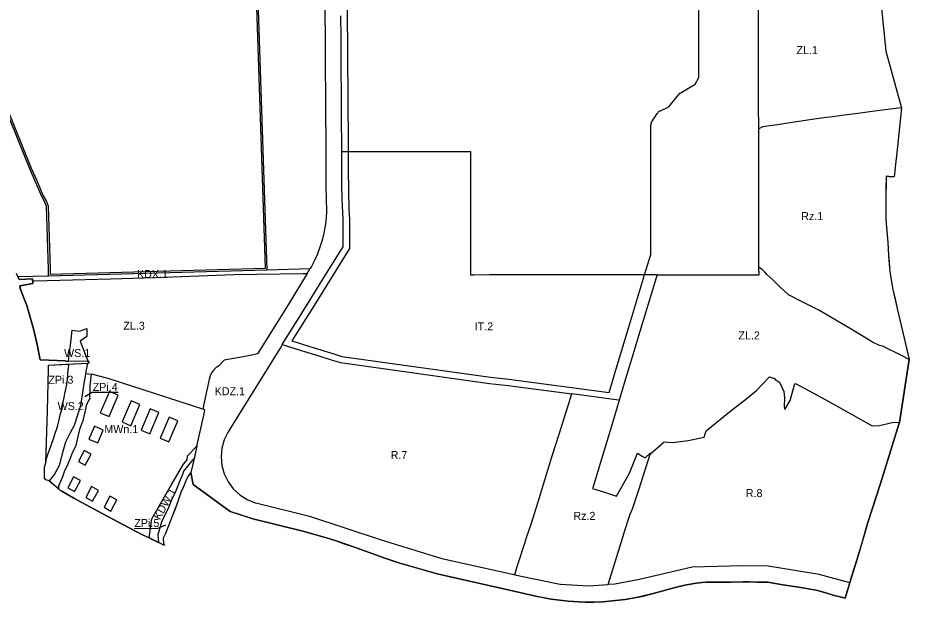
# Model space of a CAD drawing. Extents: x 7434685 to 7436459, y 5545868 to 5548111.
# Drawn here: x 7435281 to 7436395, y 5545868 to 5546598 of the extents above; entities that cross this region are included whole.
import ezdxf

# ---------------------------------------------------------------- set-up
doc = ezdxf.new("R2010")
doc.units = 0
for name, color, linetype in [('LIN_Granica Planu', 7, 'Continuous'), ('LIN_linia regulacyjna_1', 7, 'Continuous'), ('LIN_Linia Zabudowy Nieprzekraczalna', 7, 'Continuous'), ('LIN_Linia Zabudowy Obowiązujaca', 7, 'Continuous'), ('LIN_Linie Rozgraniczajace', 7, 'Continuous'), ('TXT_Oznaczenia Przeznaczenia', 7, 'Continuous')]:
    doc.layers.add(name, color=color, linetype=linetype)

msp = doc.modelspace()

# ---------------------------------------------------------------- linework, layer by layer
at = {"layer": 'LIN_Granica Planu'}
msp.add_lwpolyline([(7436359.2, 5546623), (7436366, 5546556.9), (7436385.4, 5546486.1), (7436382, 5546453.8), (7436380.6, 5546437.9), (7436378, 5546415.1), (7436376.2, 5546399.7), (7436370.9, 5546400), (7436368.3, 5546400.3), (7436366.1, 5546400.5), (7436365.8, 5546367.1), (7436365.7, 5546347.3), (7436365.8, 5546346.4), (7436368.5, 5546317.8), (7436369.3, 5546301.6), (7436370.6, 5546285.6), (7436371.2, 5546279.2), (7436373.8, 5546263.5), (7436374.6, 5546259), (7436380.1, 5546235.4), (7436395, 5546171.7), (7436383, 5546092.9), (7436381, 5546086.6), (7436359.3, 5546016.7), (7436348.6, 5545984.5), (7436343.5, 5545967.9), (7436340.8, 5545959.2), (7436329.7, 5545921), (7436322.1, 5545897.1), (7436314.8, 5545873.5), (7436307, 5545875.5), (7436303.1, 5545876.5), (7436298.9, 5545877.6), (7436292, 5545879.8), (7436285.1, 5545881.6), (7436278.7, 5545883.3), (7436254.1, 5545887.4), (7436236.9, 5545890.2), (7436218.2, 5545893.3), (7436210, 5545893.4), (7436204.4, 5545893.6), (7436195.5, 5545893.7), (7436187.6, 5545893.7), (7436171.9, 5545893.5), (7436141.3, 5545893.2), (7436136.1, 5545892.8), (7436128.9, 5545892.2), (7436114.8, 5545889.8), (7436102.7, 5545886.7), (7436076.9, 5545879.5), (7436056.3, 5545874.6), (7436040.1, 5545871.7), (7436012, 5545868.8), (7435990.1, 5545868.4), (7435969, 5545869.6), (7435947.7, 5545872.2), (7435941, 5545873.5), (7435929.9, 5545875.7), (7435895.6, 5545883.4), (7435805, 5545903.8), (7435758.6, 5545917.2), (7435741, 5545922.8), (7435700.5, 5545937.4), (7435681.5, 5545944), (7435670.8, 5545947.4), (7435637.1, 5545957.2), (7435574.8, 5545972.5), (7435546.3, 5545981.8), (7435500.1, 5546015.5), (7435497.3, 5546030.5), (7435494.1, 5546025.8), (7435492, 5546021.9), (7435488.4, 5546013.9), (7435485, 5546005.4), (7435480.7, 5545993.1), (7435474.5, 5545976.5), (7435465.7, 5545954.4), (7435462.6, 5545948.3), (7435463, 5545941.4), (7435464.3, 5545939.3), (7435445.4, 5545948.6), (7435437.9, 5545952.3), (7435420.4, 5545961.1), (7435386.4, 5545979.1), (7435351.1, 5545998.5), (7435336, 5546007.2), (7435333.1, 5546008.8), (7435320.4, 5546019.9), (7435316.3, 5546021.2), (7435314.3, 5546023.2), (7435314.4, 5546036.9), (7435315.9, 5546042.6), (7435318.2, 5546107.6), (7435319.4, 5546160.4), (7435319.5, 5546164.4), (7435341.2, 5546165.6), (7435370, 5546167.2), (7435369.9, 5546169.3), (7435340.8, 5546169.4), (7435340.7, 5546170.1), (7435309.2, 5546171), (7435305.4, 5546190.4), (7435300.5, 5546210.1), (7435292.2, 5546239), (7435284.3, 5546259), (7435283.7, 5546263.5), (7435300, 5546266.6), (7435299.5, 5546272.5), (7435282.7, 5546271.5), (7435279.4, 5546278.9)], dxfattribs=at)
at = {"layer": 'LIN_linia regulacyjna_1'}
msp.add_lwpolyline([(7435243.6, 5546543.7), (7435297.9, 5546410.5), (7435304.7, 5546395.2), (7435312.3, 5546376.8), (7435316.9, 5546368.8), (7435318.9, 5546363), (7435321.5, 5546284.9), (7435321.5, 5546278.2), (7435590.7, 5546285.6), (7435571.7, 5546849.8), (7435571.7, 5546850.9), (7435567.9, 5546853), (7435538.3, 5546859.6), (7435397.1, 5546854.4), (7435356.3, 5546852.2), (7435331.6, 5546851.4), (7435319.9, 5546850.7), (7435306.9, 5546850.4), (7435208.7, 5546851.2)], dxfattribs=at)
at = {"layer": 'LIN_Linia Zabudowy Nieprzekraczalna'}
for p, q in [((7436073.4, 5546468.7), (7436080.1, 5546479)), ((7436072, 5546302.7), (7436072, 5546464.3)), ((7436064.4, 5546277.4), (7436072, 5546302.7)), ((7435894.7, 5546146.9), (7436019.9, 5546130.4)), ((7435395.5, 5546131.6), (7435384.2, 5546105.1)), ((7435406.6, 5546126.9), (7435395.5, 5546131.6)), ((7435395.3, 5546100.4), (7435406.6, 5546126.9)), ((7435422.6, 5546120.1), (7435411.3, 5546093.6)), ((7435433.6, 5546115.3), (7435422.6, 5546120.1)), ((7435422.3, 5546088.9), (7435433.6, 5546115.3)), ((7435446.4, 5546109.9), (7435435.1, 5546083.4)), ((7435457.4, 5546105.2), (7435446.4, 5546109.9)), ((7435384.2, 5546105.1), (7435395.3, 5546100.4)), ((7435446.1, 5546078.7), (7435457.4, 5546105.2)), ((7435470.2, 5546099.7), (7435458.9, 5546073.3)), ((7435481.2, 5546095), (7435470.2, 5546099.7)), ((7435376.8, 5546088.2), (7435369.9, 5546072.2)), ((7435387.9, 5546083.5), (7435376.8, 5546088.2)), ((7435411.3, 5546093.6), (7435422.3, 5546088.9)), ((7435469.9, 5546068.6), (7435481.2, 5546095)), ((7435381, 5546067.4), (7435387.9, 5546083.5)), ((7435435.1, 5546083.4), (7435446.1, 5546078.7)), ((7435458.9, 5546073.3), (7435469.9, 5546068.6)), ((7435369.9, 5546072.2), (7435381, 5546067.4))]:
    msp.add_line(p, q, dxfattribs=at)
for points in [[(7435766.5, 5546953.9), (7435690.6, 5546953.9), (7435692.1, 5546706.5), (7435692.3, 5546682.4), (7435692.6, 5546636), (7435692.7, 5546624), (7435692.8, 5546608.2), (7435693.9, 5546441.6), (7435693.9, 5546431.1), (7435693.9, 5546431.1), (7435694, 5546410.7), (7435694.2, 5546381.2), (7435694.9, 5546359.7), (7435695.6, 5546346.7), (7435695.4, 5546331.7), (7435695.7, 5546310.3), (7435684.1, 5546291.7), (7435651.3, 5546239), (7435648.5, 5546234.6), (7435646.4, 5546231.2), (7435623.7, 5546194.8)], [(7436132, 5546524.1), (7436132, 5546850.9), (7435957.9, 5546850.9), (7435957.9, 5546872.1), (7435914, 5546872.1)], [(7436108.8, 5546504.2), (7436127.7, 5546515.4), (7436132, 5546524.1)], [(7436083.2, 5546481.7), (7436094.7, 5546487.4), (7436106.7, 5546502.3)], [(7436019.9, 5546130.4), (7436030.1, 5546164.1), (7436044.2, 5546210.8), (7436064.4, 5546277.4)], [(7435623.7, 5546194.8), (7435644.6, 5546188.4), (7435652.5, 5546185.9)], [(7435652.6, 5546185.9), (7435653.1, 5546185.8), (7435670, 5546180.5)], [(7435670.1, 5546180.5), (7435674.9, 5546178.9), (7435686.2, 5546175.5), (7435871.6, 5546149.7), (7435894.7, 5546146.9)]]:
    msp.add_lwpolyline(points, dxfattribs=at)
for centre, start, end in [((7436112.9, 5546497.3), 120.7481, 141.1626), ((7436086.8, 5546474.6), 116.4028, 146.5734), ((7436080, 5546464.3), 146.5734, 180), ((7435650.2, 5546178.3), 72.4201, 72.8733), ((7435667.6, 5546172.9), 71.9926, 72.8461), ((7435893.7, 5546138.9), 82.5116, 82.9419)]:
    msp.add_arc(centre, 8, start, end, dxfattribs=at)
at = {"layer": 'LIN_Linia Zabudowy Obowiązujaca'}
for p, q in [((7435364.2, 5546057.9), (7435356.8, 5546044.2)), ((7435372.8, 5546053.2), (7435364.2, 5546057.9)), ((7435365.4, 5546039.5), (7435372.8, 5546053.2)), ((7435356.8, 5546044.2), (7435365.4, 5546039.5)), ((7435350.8, 5546024.9), (7435343.5, 5546011.3)), ((7435359.4, 5546020.3), (7435350.8, 5546024.9)), ((7435352.1, 5546006.7), (7435359.4, 5546020.3)), ((7435343.5, 5546011.3), (7435352.1, 5546006.7)), ((7435373.3, 5546012.8), (7435366, 5545999.2)), ((7435381.9, 5546008.1), (7435373.3, 5546012.8)), ((7435374.6, 5545994.5), (7435381.9, 5546008.1)), ((7435366, 5545999.2), (7435374.6, 5545994.5)), ((7435396.2, 5546000.7), (7435388.8, 5545986.9)), ((7435404.7, 5545996.1), (7435396.2, 5546000.7)), ((7435397.3, 5545982.3), (7435404.7, 5545996.1)), ((7435388.8, 5545986.9), (7435397.3, 5545982.3))]:
    msp.add_line(p, q, dxfattribs=at)
at = {"layer": 'LIN_Linie Rozgraniczajace'}
msp.add_line((7435368.8, 5546169.3), (7435344.6, 5546169.4), dxfattribs=at)
for points in [[(7435592.7, 5546283.7), (7435573.9, 5546846), (7435555.2, 5547402.9)], [(7436356.5, 5546690.7), (7436356.8, 5546682.9), (7436357.1, 5546675), (7436359.2, 5546623), (7436366, 5546556.9), (7436385.4, 5546486.1)], [(7435664.8, 5546608.6), (7435665, 5546569.7), (7435665.2, 5546551.1), (7435665.3, 5546530.9), (7435665.4, 5546506.8), (7435665.7, 5546469.7), (7435665.8, 5546454.4), (7435665.8, 5546447.8), (7435665.9, 5546431.5), (7435665.9, 5546428.7), (7435666, 5546422.6), (7435666, 5546422.6), (7435665.9, 5546420.8), (7435665.8, 5546419), (7435665.8, 5546418.5), (7435665.8, 5546415.8), (7435665.8, 5546414), (7435665.8, 5546412.2), (7435665.8, 5546411.3), (7435665.8, 5546410.5), (7435665.9, 5546408.7), (7435665.9, 5546406.9), (7435666, 5546405.2), (7435666, 5546403.4), (7435666.1, 5546400.5), (7435666.1, 5546398.9), (7435666.1, 5546397.9), (7435666.1, 5546396.2), (7435666.1, 5546394.4), (7435666.2, 5546392.6), (7435666.2, 5546390.8), (7435666.2, 5546389.1), (7435666.2, 5546387.3), (7435666.2, 5546386.9), (7435666.3, 5546372.6), (7435666.5, 5546367.9), (7435666.7, 5546362), (7435666.7, 5546356), (7435666.3, 5546348.9), (7435665.9, 5546344.5), (7435665.2, 5546338.7), (7435664.4, 5546334.3), (7435662.9, 5546326.9), (7435661, 5546319.5), (7435659.5, 5546314.6), (7435655.1, 5546302.5), (7435651.8, 5546295.1), (7435651, 5546293.5), (7435649.8, 5546291.2), (7435647.9, 5546287.6), (7435646.4, 5546285.1)], [(7436206.9, 5546459.9), (7436206.9, 5546468.1), (7436206.9, 5546471.8), (7436206.9, 5546471.8), (7436206.8, 5546477.2), (7436206.8, 5546481.7), (7436206.8, 5546486.2), (7436206.5, 5546613.2)], [(7435685.9, 5546431.1), (7435685.8, 5546441), (7435685.8, 5546441.6), (7435685.8, 5546447.4), (7435685.8, 5546453.9), (7435685.7, 5546456.6), (7435685.7, 5546457.7), (7435685.7, 5546469.2), (7435685.4, 5546506.3), (7435685.4, 5546515.3), (7435685.3, 5546521.7), (7435685.3, 5546522.2), (7435685.3, 5546530.5), (7435685.3, 5546534.1), (7435685.2, 5546550.6), (7435685, 5546569.3), (7435685, 5546574.3), (7435684.8, 5546600.8)], [(7435319.5, 5546276.2), (7435319.5, 5546284.9), (7435316.9, 5546362.6), (7435315, 5546368), (7435310.5, 5546375.9), (7435302.8, 5546394.4), (7435296.1, 5546409.7), (7435281.8, 5546444.7), (7435241.8, 5546543)], [(7436385.4, 5546486.1), (7436385.4, 5546486.1), (7436385.4, 5546486.1), (7436375.1, 5546484.8), (7436364.9, 5546483.6), (7436354.8, 5546482.3), (7436342.7, 5546480.7), (7436330.7, 5546479), (7436320.7, 5546477.8), (7436310.7, 5546476.5), (7436299.4, 5546474.9), (7436288.2, 5546473.4), (7436279.5, 5546472.2), (7436270.8, 5546471.1), (7436257.1, 5546468.9), (7436243.3, 5546466.7), (7436230.6, 5546464.9), (7436230.6, 5546464.9), (7436224.2, 5546464), (7436217.8, 5546463.2), (7436214.8, 5546462.7), (7436211.8, 5546462.3), (7436206.9, 5546459.9)], [(7436385.4, 5546486.1), (7436383.7, 5546469.9), (7436382, 5546453.8), (7436381.3, 5546445.8), (7436380.6, 5546437.9), (7436379.2, 5546425.9), (7436378, 5546415.1), (7436377.1, 5546407.4), (7436376.2, 5546399.7), (7436370.9, 5546400), (7436369.6, 5546400.2), (7436368.3, 5546400.3), (7436367.2, 5546400.4), (7436366.1, 5546400.5), (7436365.9, 5546383.8), (7436365.8, 5546367.1), (7436365.8, 5546357.2), (7436365.7, 5546347.3), (7436365.8, 5546346.4), (7436365.8, 5546346.4), (7436367.2, 5546332.1), (7436368.5, 5546317.8), (7436369.3, 5546301.6), (7436370, 5546293.6), (7436370.6, 5546285.6), (7436370.9, 5546282.4), (7436371.2, 5546279.2), (7436373.8, 5546263.5), (7436374.6, 5546259), (7436377.3, 5546247.2), (7436380.1, 5546235.4), (7436387.5, 5546203.6), (7436395, 5546171.7)], [(7436207.3, 5546286.9), (7436207.3, 5546298.2), (7436207.3, 5546309.5), (7436207.2, 5546331.8), (7436207.2, 5546354.1), (7436207.1, 5546374), (7436207.1, 5546393.8), (7436207, 5546402.2), (7436207, 5546410.6), (7436206.9, 5546435.2), (7436206.9, 5546459.9)], [(7435611.6, 5546190.5), (7435634.6, 5546227.3), (7435640.7, 5546237.1), (7435641.5, 5546238.4), (7435641.7, 5546238.8), (7435649.6, 5546251.5), (7435659, 5546266.5), (7435679.7, 5546299.7), (7435681.7, 5546303.2), (7435687.6, 5546312.5), (7435687.6, 5546346.5), (7435686.3, 5546372.2), (7435686.2, 5546389.8), (7435686.2, 5546389.9), (7435686.1, 5546399.6), (7435686, 5546421.6), (7435685.9, 5546428.2), (7435685.9, 5546431.1)], [(7436080, 5546277.4), (7436076.2, 5546277.4), (7436020.8, 5546277.3), (7436002.6, 5546277.3), (7435990.7, 5546277.3), (7435979.9, 5546277.3), (7435958.1, 5546277.3), (7435922, 5546277.2), (7435902.8, 5546277.2), (7435888.6, 5546277.2), (7435888.6, 5546277.2), (7435870, 5546277.2), (7435851, 5546277.1), (7435847.3, 5546277.1), (7435847.2, 5546342.3), (7435847.2, 5546368.2), (7435847.1, 5546431.1), (7435819.5, 5546431.1), (7435819.5, 5546431), (7435796.9, 5546431.1), (7435775.1, 5546431.1), (7435753.4, 5546431.1), (7435685.9, 5546431.1)], [(7435592.7, 5546283.7), (7435646.4, 5546285.1)], [(7435642.7, 5546279), (7435644.7, 5546282.2), (7435646.4, 5546285.1)], [(7436080, 5546277.4), (7436091.2, 5546277.4), (7436207.4, 5546277.5), (7436207.3, 5546286.9)], [(7436395, 5546171.7), (7436386.1, 5546176.2), (7436377.2, 5546180.6), (7436370.1, 5546184.2), (7436363, 5546187.7), (7436357.8, 5546189.2), (7436349.3, 5546193.4), (7436341.8, 5546198), (7436334.3, 5546202.6), (7436334.3, 5546202.6), (7436322.4, 5546209.6), (7436310.4, 5546216.7), (7436282.2, 5546233.4), (7436263.1, 5546242.8), (7436244.1, 5546252.2), (7436232.9, 5546263), (7436225.1, 5546270.5), (7436217.3, 5546277.9), (7436214.4, 5546280.8), (7436211.6, 5546283.7), (7436207.3, 5546286.9)], [(7435281.1, 5546275.1), (7435319.5, 5546276.2)], [(7435281.1, 5546275.1), (7435282.7, 5546271.5), (7435299.5, 5546272.5), (7435299.8, 5546269.5)], [(7435299.8, 5546269.5), (7435301.8, 5546269.7), (7435397, 5546272.2), (7435453.2, 5546274.2), (7435551.1, 5546277.6), (7435637.7, 5546278.9), (7435642.7, 5546279)], [(7435319.5, 5546276.2), (7435592.7, 5546283.7)], [(7435642.7, 5546279), (7435618.8, 5546239.8), (7435580.7, 5546178.6), (7435571.4, 5546176.7), (7435558.1, 5546174.1), (7435555.7, 5546173.6), (7435539.1, 5546170.9), (7435532.2, 5546163.8), (7435528.7, 5546161.2), (7435525.5, 5546158.1), (7435523.1, 5546154.8), (7435521.4, 5546151.3), (7435520, 5546146.4), (7435517.2, 5546133.3), (7435513.9, 5546117.7), (7435512.2, 5546109.4)], [(7436080, 5546277.4), (7436078.9, 5546273.5), (7436058.6, 5546206.5), (7436048.6, 5546173.4), (7436044.4, 5546159.8), (7436032.6, 5546120.7)], [(7435299.8, 5546269.5), (7435300, 5546266.6), (7435283.7, 5546263.5), (7435284.3, 5546259), (7435292.2, 5546239), (7435300.5, 5546210.1), (7435305.4, 5546190.4), (7435309.2, 5546171), (7435340.7, 5546170.1), (7435340.8, 5546169.4), (7435344.6, 5546169.4)], [(7435344.6, 5546169.4), (7435345.4, 5546177.6), (7435347.3, 5546192.8), (7435349.1, 5546208.1), (7435358.3, 5546206.8), (7435362.8, 5546208.7), (7435367.2, 5546210.5), (7435367.2, 5546205.5), (7435367.2, 5546200.5), (7435363.2, 5546197.5), (7435359.2, 5546194.5), (7435365.3, 5546178.4), (7435367.1, 5546173.9), (7435368.8, 5546169.3)], [(7435611.6, 5546190.5), (7435610.1, 5546188), (7435560, 5546107.6), (7435543.9, 5546081.2), (7435539.1, 5546071.4), (7435536.2, 5546060.9), (7435535.2, 5546050), (7435536.2, 5546039.1), (7435539.1, 5546028.6), (7435543.9, 5546018.8), (7435550.4, 5546010), (7435558.4, 5546002.6), (7435567.6, 5545996.7), (7435577.7, 5545992.6), (7435580.1, 5545991.9), (7435645.4, 5545975.7), (7435735.2, 5545946.2), (7435810.9, 5545923), (7435899.1, 5545903.2), (7435902.1, 5545902.6)], [(7435611.6, 5546190.5), (7435612.6, 5546190.1), (7435615.4, 5546189), (7435616.8, 5546188.6), (7435635, 5546183), (7435640.5, 5546181.3), (7435641, 5546181.2), (7435650.2, 5546178.3), (7435654.9, 5546176.8), (7435672.5, 5546171.3), (7435684.5, 5546167.7), (7435870.6, 5546141.8), (7435893.7, 5546138.9), (7435973.4, 5546128.5)], [(7435315.9, 5546042.6), (7435316.4, 5546045.3), (7435316.8, 5546048), (7435319, 5546054), (7435321.2, 5546059.9), (7435322.7, 5546064.2), (7435324.1, 5546068.5), (7435325.5, 5546072.5), (7435326.9, 5546076.5), (7435328.3, 5546080.7), (7435329.7, 5546084.9), (7435331, 5546089.7), (7435332.4, 5546094.6), (7435333.3, 5546098.5), (7435334.2, 5546102.4), (7435335.2, 5546106.2), (7435336.3, 5546110), (7435337.1, 5546114.4), (7435337.9, 5546118.8), (7435339, 5546124), (7435340, 5546129.2), (7435341.2, 5546134.7), (7435342.4, 5546140.2), (7435342.7, 5546143.7), (7435343.1, 5546147.2), (7435343.6, 5546152.7), (7435344.1, 5546158.1), (7435344.7, 5546163.6), (7435344, 5546165.4), (7435344, 5546165.8)], [(7435315.9, 5546042.6), (7435318.2, 5546107.6), (7435319.4, 5546160.4), (7435319.5, 5546164.4), (7435335.8, 5546165.3), (7435341.2, 5546165.6), (7435344, 5546165.8)], [(7435344, 5546165.8), (7435368.2, 5546167.1)], [(7435368.2, 5546167.1), (7435367.2, 5546162.8), (7435365.7, 5546153.9)], [(7435368.8, 5546169.3), (7435369.9, 5546169.3), (7435370, 5546167.2), (7435368.2, 5546167.1)], [(7436383, 5546092.9), (7436395, 5546171.7)], [(7435365.7, 5546153.9), (7435365.6, 5546153.4), (7435364, 5546144), (7435362.7, 5546135.8), (7435360.6, 5546122.2), (7435358.9, 5546112.5), (7435351.5, 5546089.1), (7435346.7, 5546080.1), (7435340.6, 5546068.2), (7435336.5, 5546053.7), (7435332.8, 5546039.3), (7435327, 5546028.5), (7435320.4, 5546019.9)], [(7435332.5, 5546009.4), (7435332.2, 5546013.7), (7435337.4, 5546025.3), (7435339.4, 5546031.5), (7435343.4, 5546040.5), (7435347.2, 5546049.7), (7435349.7, 5546056.1), (7435353.8, 5546064.3), (7435356.6, 5546075.2), (7435359.2, 5546085.6), (7435362.1, 5546093.1), (7435362.7, 5546094.9), (7435364.9, 5546104), (7435366.3, 5546111), (7435367, 5546114.9), (7435369.6, 5546119.7), (7435371.7, 5546122.8), (7435371.1, 5546125.5), (7435371.3, 5546133.1), (7435371.4, 5546137.1), (7435371.7, 5546138.5), (7435372.3, 5546146.3), (7435373, 5546153.1)], [(7435365.7, 5546153.9), (7435369.3, 5546153.5), (7435373, 5546153.1), (7435373, 5546153.1)], [(7435512.2, 5546109.4), (7435394, 5546147.9), (7435373.3, 5546153.1), (7435373, 5546153.1)], [(7436071.3, 5546053.3), (7436088.8, 5546068.8), (7436099.6, 5546067.8), (7436119, 5546070.4), (7436138.8, 5546074.6), (7436141.1, 5546082.3), (7436170.5, 5546106.1), (7436185.6, 5546117.7), (7436186.2, 5546118.3), (7436195.3, 5546125.7), (7436204, 5546132.8), (7436220.4, 5546150), (7436226.5, 5546147.9), (7436227.7, 5546146.4), (7436233.1, 5546143.1), (7436238.2, 5546131.5), (7436239.3, 5546123.9), (7436238.8, 5546112.9), (7436239.7, 5546109), (7436246.3, 5546120.5), (7436251.5, 5546140.1), (7436252.9, 5546141.7), (7436270.1, 5546132.5), (7436291, 5546121.4), (7436348.8, 5546088.6), (7436357.7, 5546089), (7436375.6, 5546093.1), (7436380.8, 5546092.9), (7436383, 5546092.9)], [(7435902.1, 5545902.6), (7435905.2, 5545913), (7435914.5, 5545942.2), (7435917.3, 5545950.6), (7435922.4, 5545965.9), (7435922.4, 5545965.9), (7435931.2, 5545993.9), (7435938.5, 5546017.1), (7435949.2, 5546052.5), (7435957.4, 5546078.3), (7435973.4, 5546128.5)], [(7436032.6, 5546120.7), (7436028.7, 5546121.2), (7435973.4, 5546128.5)], [(7436032.6, 5546120.7), (7436026.6, 5546101), (7435999.5, 5546011.2), (7435999.3, 5546010.6), (7436014.3, 5546005.8), (7436029.3, 5546001), (7436045.3, 5546029.7), (7436055.6, 5546054.4), (7436061.4, 5546050.9), (7436065.1, 5546048.9), (7436071.8, 5546054.9), (7436071.3, 5546053.3)], [(7435504.8, 5546063.5), (7435514.1, 5546103.9), (7435515, 5546108.5), (7435512.2, 5546109.4)], [(7436320.7, 5545892.6), (7436322.1, 5545897.1), (7436325.9, 5545909.1), (7436329.7, 5545921), (7436335.3, 5545940.1), (7436340.8, 5545959.2), (7436343.5, 5545967.9), (7436348.6, 5545984.5), (7436348.6, 5545984.5), (7436359.3, 5546016.7), (7436381, 5546086.6), (7436381, 5546086.6), (7436383, 5546092.9)], [(7435445.4, 5545948.6), (7435448.4, 5545972.6), (7435472.7, 5546014.6), (7435488, 5546041), (7435492.6, 5546046.2), (7435493, 5546051.1), (7435504.8, 5546063.5)], [(7435504.8, 5546063.5), (7435501.3, 5546047.8)], [(7436018.7, 5545890.3), (7436038.8, 5545955), (7436039, 5545955.5), (7436046.5, 5545978.5), (7436049.1, 5545985.1), (7436057.6, 5546010.1), (7436071.3, 5546053.3)], [(7435320.4, 5546019.9), (7435316.3, 5546021.2), (7435314.3, 5546023.2), (7435314.4, 5546036.9), (7435315.9, 5546042.6)], [(7435501.3, 5546047.8), (7435499.4, 5546045.8), (7435496.9, 5546043), (7435493.3, 5546038.5), (7435488.2, 5546032.2), (7435486.7, 5546028), (7435485.6, 5546025.1), (7435484.3, 5546021.9), (7435480.2, 5546011.7), (7435477.6, 5546005.4), (7435475.4, 5546000.6), (7435472.8, 5545994.9), (7435471.5, 5545991.5), (7435470, 5545987.6), (7435463.1, 5545973.6), (7435460.6, 5545968.3), (7435456.2, 5545952.7), (7435456.7, 5545943)], [(7435501.3, 5546047.8), (7435497.3, 5546030.5)], [(7435497.3, 5546030.5), (7435497.3, 5546030.5), (7435497.3, 5546030.5), (7435495.7, 5546028.2), (7435494.1, 5546025.8), (7435492, 5546021.9), (7435490.2, 5546017.9), (7435488.4, 5546013.9), (7435486.7, 5546009.7), (7435485, 5546005.4), (7435482.9, 5545999.3), (7435480.7, 5545993.1), (7435477.6, 5545984.8), (7435474.5, 5545976.5), (7435465.7, 5545954.4), (7435464.8, 5545952.6), (7435462.6, 5545948.3), (7435463, 5545941.4), (7435463, 5545941.4), (7435464.3, 5545939.3), (7435457, 5545942.9), (7435456.7, 5545943)], [(7435497.3, 5546030.5), (7435500.1, 5546015.5), (7435546.3, 5545981.8), (7435547, 5545981.6), (7435574.8, 5545972.5), (7435637.1, 5545957.2), (7435664, 5545949.6), (7435670.8, 5545947.4), (7435681.5, 5545944), (7435686.4, 5545942.3), (7435700.5, 5545937.4), (7435741, 5545922.8), (7435744.9, 5545921.6), (7435758.6, 5545917.2), (7435773.4, 5545913), (7435805, 5545903.8), (7435895.6, 5545883.4), (7435929.9, 5545875.7), (7435935.5, 5545874.8), (7435941, 5545873.5), (7435947.7, 5545872.2), (7435969, 5545869.6), (7435975.2, 5545869.2), (7435990.1, 5545868.4), (7436000.8, 5545868.6), (7436012, 5545868.8), (7436040.1, 5545871.7), (7436056.3, 5545874.6), (7436061, 5545875.7), (7436076.9, 5545879.5), (7436102.7, 5545886.7), (7436114.8, 5545889.8), (7436128.9, 5545892.2), (7436136.1, 5545892.8), (7436141.3, 5545893.2), (7436171.9, 5545893.5), (7436187.6, 5545893.7), (7436192.6, 5545893.7), (7436195.5, 5545893.7), (7436204.4, 5545893.6), (7436210, 5545893.4), (7436218.2, 5545893.3), (7436236.9, 5545890.2), (7436254.1, 5545887.4), (7436278.7, 5545883.3), (7436285.1, 5545881.6), (7436292, 5545879.8), (7436298.9, 5545877.6), (7436303.1, 5545876.5), (7436307, 5545875.5), (7436314.8, 5545873.5), (7436320.7, 5545892.6)], [(7435320.4, 5546019.9), (7435326.8, 5546014.4), (7435332.5, 5546009.4), (7435332.5, 5546009.4)], [(7435332.5, 5546009.4), (7435333.1, 5546008.8), (7435336, 5546007.2), (7435351.1, 5545998.5), (7435386.4, 5545979.1), (7435420.4, 5545961.1), (7435437.9, 5545952.3), (7435445.4, 5545948.6)], [(7435445.4, 5545948.6), (7435448.3, 5545947.1), (7435452.7, 5545945), (7435456.7, 5545943)], [(7436320.7, 5545892.6), (7436282.5, 5545903), (7436249.5, 5545908.5), (7436218.8, 5545913.5), (7436186.4, 5545914), (7436123.9, 5545912.2), (7436058, 5545896.6), (7436027.2, 5545890.8), (7436018.7, 5545890.3), (7436018.7, 5545890.3)], [(7435902.1, 5545902.6), (7435954.8, 5545891.9), (7435958.4, 5545891.1), (7435959.2, 5545891.1), (7435994.3, 5545888.8), (7436018.7, 5545890.3)]]:
    msp.add_lwpolyline(points, dxfattribs=at)
at = {"layer": 'TXT_Oznaczenia Przeznaczenia'}
for points in [[(7435364.8, 5546125.5), (7435374.1, 5546130.7), (7435406.5, 5546130.7)], [(7435465.7, 5545964.6), (7435456, 5545960.4), (7435426.4, 5545960.2)]]:
    msp.add_lwpolyline(points, dxfattribs=at)

# ---------------------------------------------------------------- texts
for s, p in [('ZL.1', (7436254.1, 5546553.1)), ('Rz.1', (7436260.1, 5546345.8)), ('KDX.1', (7435430, 5546273.4)), ('ZL.3', (7435413, 5546208.8)), ('IT.2', (7435852.1, 5546208)), ('ZL.2', (7436181.6, 5546196.7)), ('WS.1', (7435338.9, 5546174.7)), ('ZPi.3', (7435319.3, 5546141.3)), ('ZPi.4', (7435374.7, 5546132.3)), ('KDZ.1', (7435527.1, 5546127)), ('WS.2', (7435330.8, 5546108.4)), ('MWn.1', (7435389.2, 5546079.6)), ('R.7', (7435747, 5546047.3)), ('R.8', (7436190.8, 5545999.7)), ('Rz.2', (7435975.4, 5545971.2)), ('ZPi.5', (7435426.7, 5545962.3))]:
    msp.add_text(s, height=10, dxfattribs=at).set_placement(p)
msp.add_text('KDW.1', height=10, rotation=60.8755, dxfattribs=at).set_placement((7435458.6, 5545970.4))

doc.saveas('drawing.dxf')
